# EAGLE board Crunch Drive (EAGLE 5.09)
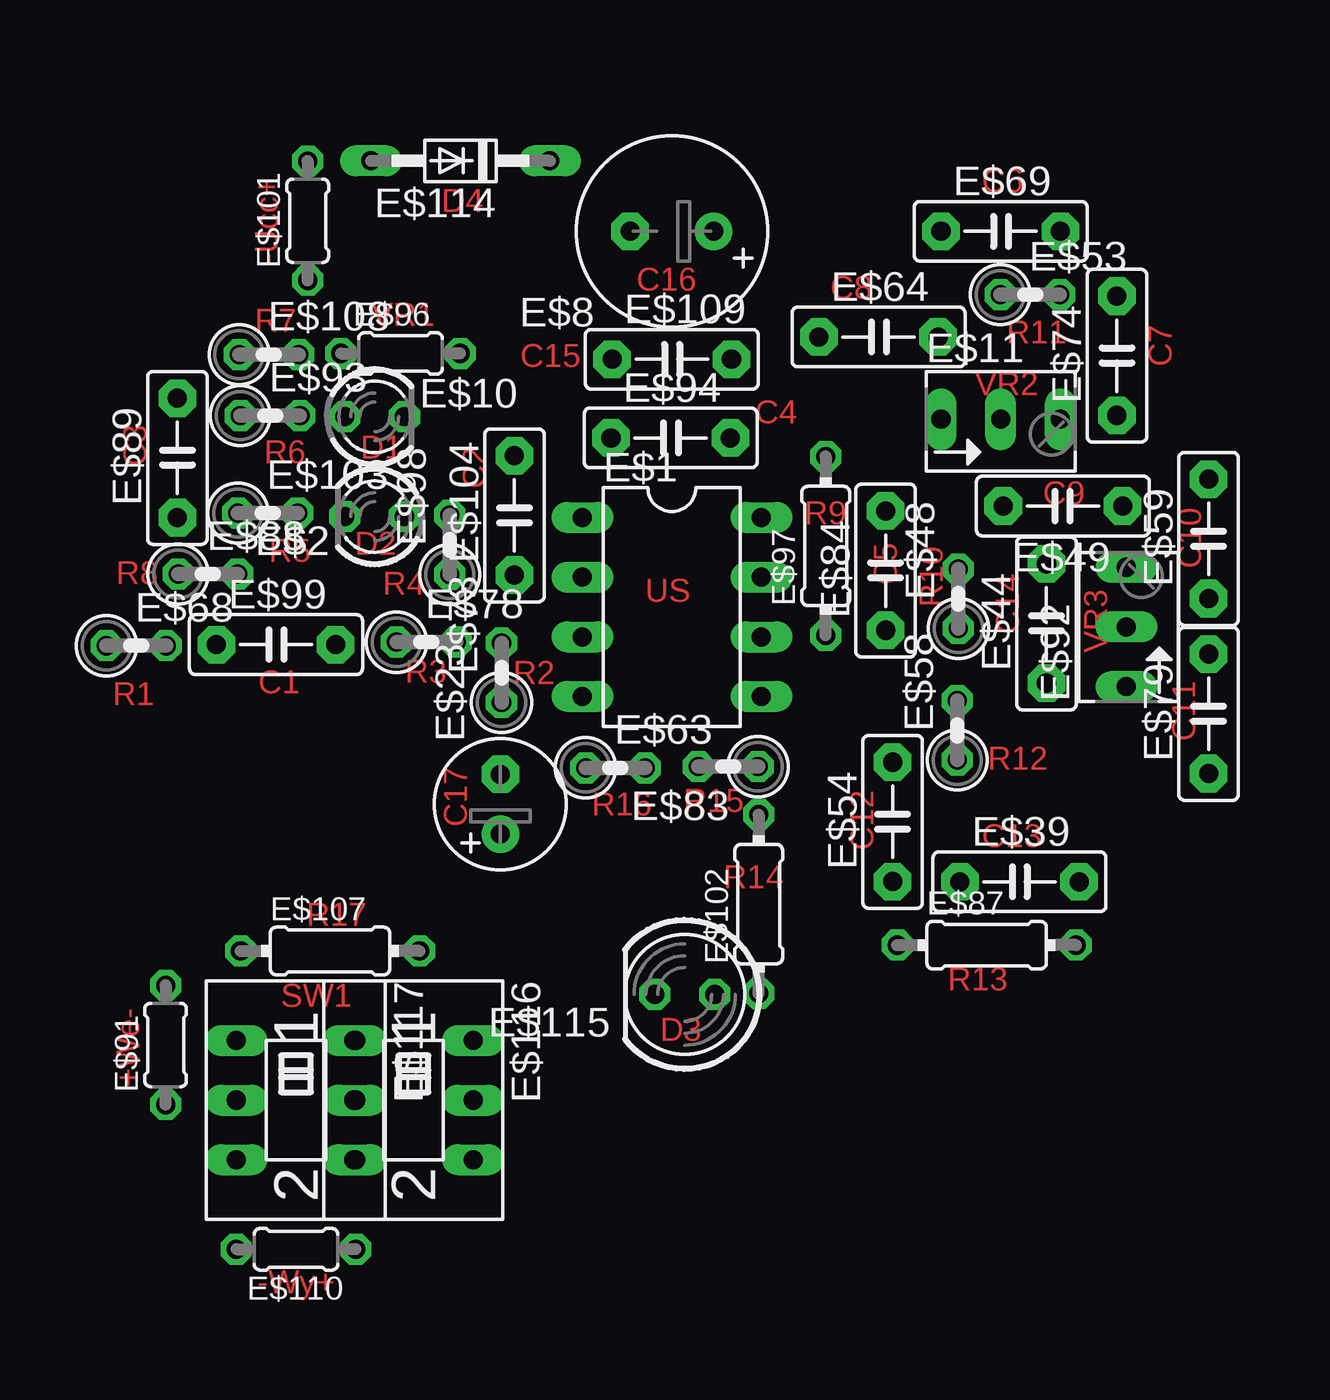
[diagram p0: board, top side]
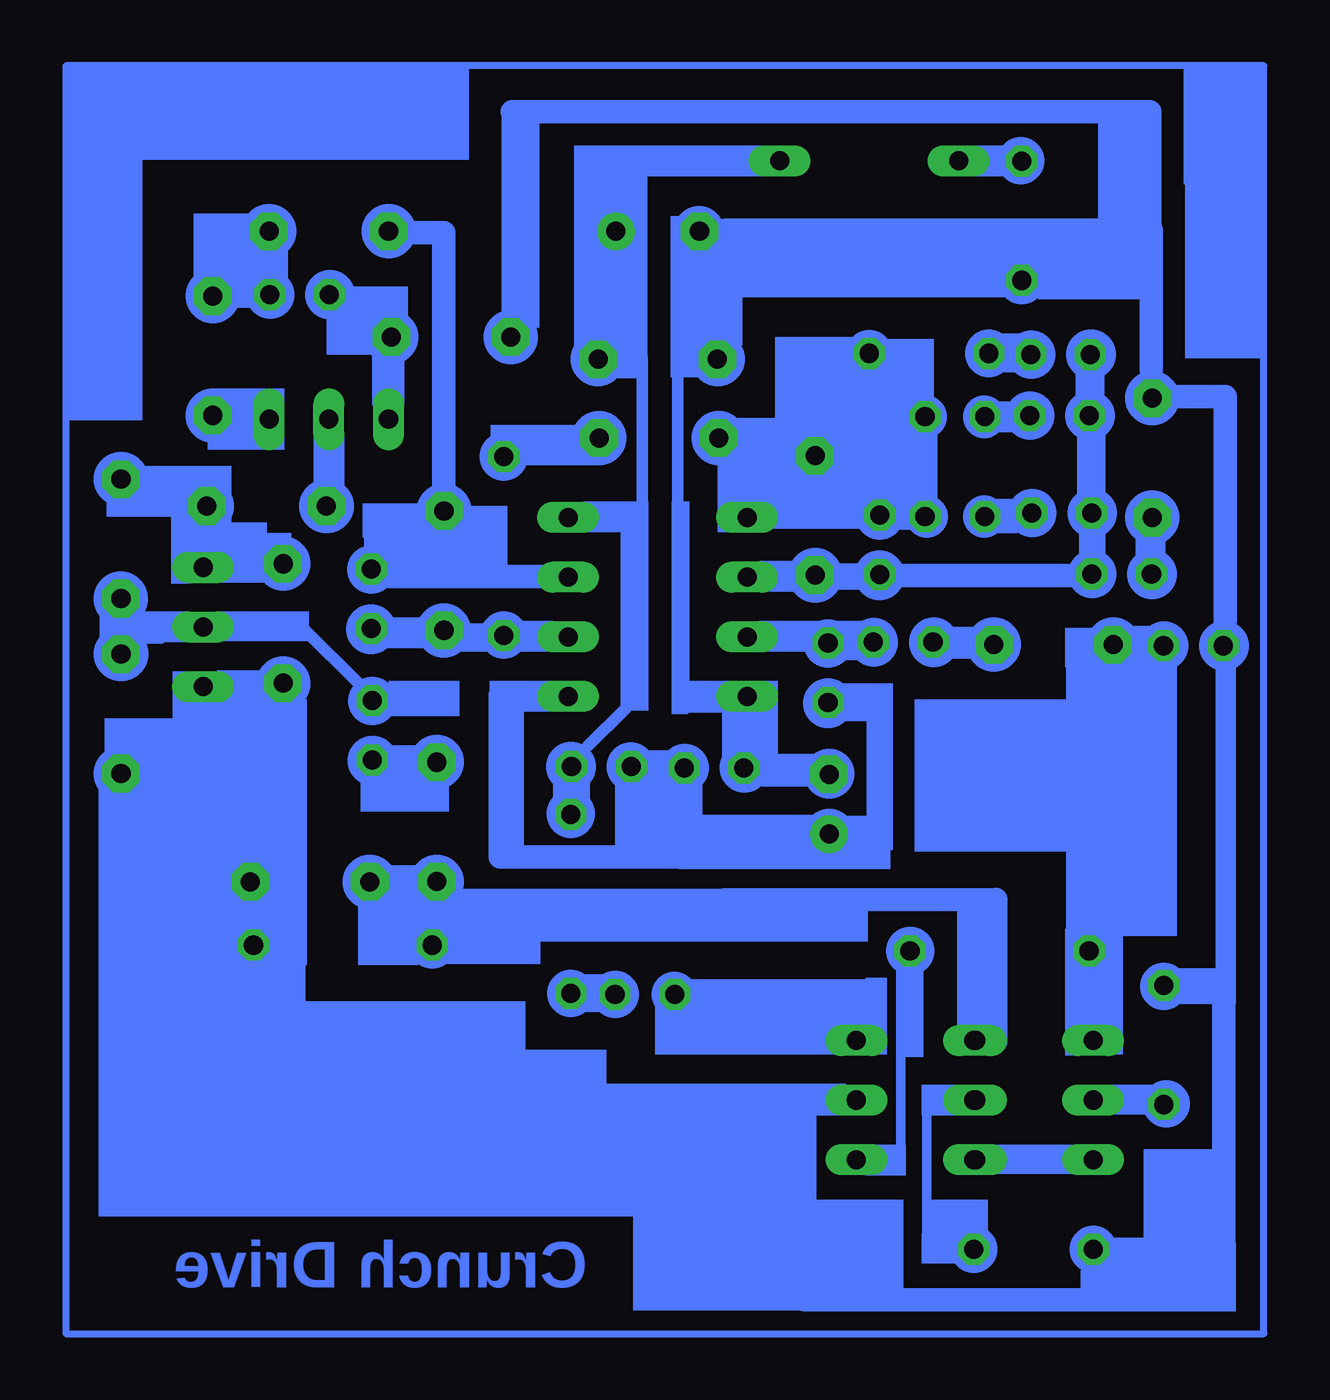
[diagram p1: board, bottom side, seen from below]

No outline drawn. Coordinates in mm, seen from the top.
Copper layers (1*16): Top 0.035mm / dielectric 1.5mm / Bottom 0.035mm
Design rules "default": minimum track width 10mil, minimum drill 24mil, track to track 8mil, track to pad 8mil, pad to pad 8mil, via to via 8mil, smd to smd 8mil, copper to edge 40mil, drill to drill 8mil, minimum pad ring 10mil, minimum via ring 8mil, stop-mask expansion 4mil, vias tented up to drill 0mil, thermal gap 10mil

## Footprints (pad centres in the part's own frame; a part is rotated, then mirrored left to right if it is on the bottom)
DIL08 = drill 0.813 long: 1 -3.81,-3.81; 2 -1.27,-3.81; 3 1.27,-3.81; 4 3.81,-3.81; 5 3.81,3.81; 6 1.27,3.81; 7 -1.27,3.81; 8 -3.81,3.81
LED3MM = drill 0.813 octagon: A -1.27,0; K 1.27,0
E3,5-8 = drill 0.813 pad 1.6 round: + -1.778,0 | drill 0.813 pad 1.6 octagon: - 1.778,0
B64Y = drill 0.813 long: A 2.54,0; E -2.54,0; S 0,0
E2,5-6 = drill 0.813 pad 1.6 round: + -1.27,0 | drill 0.813 pad 1.6 octagon: - 1.27,0
C5B2.5 = drill 0.813 pad 1.6 octagon: 1 -2.54,0; 2 2.54,0
0207/2V = drill 0.813 octagon: 1 -1.27,0; 2 1.27,0
0204/7 = drill 0.813 octagon: 1 -3.81,0; 2 3.81,0
0204/5 = drill 0.813 octagon: 1 -2.54,0; 2 2.54,0
DO34-7 = drill 0.813 long: A 3.81,0; C -3.81,0
LED5MM = drill 0.813 octagon: A -1.27,0; K 1.27,0
A68-A31 = drill 0.813 long: 1 -2.54,-2.54; 2 0,-2.54; 3 2.54,-2.54; 4 -2.54,2.54; 5 0,2.54; 6 2.54,2.54

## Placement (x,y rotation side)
E$1  [DIL08]  26,31 270 top
E$2  [LED3MM]  13.35,34.85 180 top
E$8  [E3,5-8]  26,47 180 top
E$10  [LED3MM]  13.35,39.1 0 top
E$11  [B64Y]  40,39 0 top
E$23  [E2,5-6]  18.7,22.6 90 top
E$39  [C5B2.5]  40.8,19.3 0 top
E$44  [C5B2.5]  41.95,30.3 90 top
E$48  [0207/2V]  38.2,31.35 90 top
E$49  [C5B2.5]  42.65,35.3 180 top
E$53  [0207/2V]  41.25,44.3 0 top
E$54  [C5B2.5]  35.4,21.85 90 top
E$58  [0207/2V]  38.15,25.75 90 top
E$59  [C5B2.5]  48.85,33.9 90 top
E$63  [0207/2V]  23.6,24.15 0 top
E$64  [C5B2.5]  34.8,42.5 0 top
E$68  [0207/2V]  3.2,29.35 0 top
E$69  [C5B2.5]  40,47 0 top
E$73  [0207/2V]  18.75,28.2 90 top
E$74  [C5B2.5]  44.95,41.7 90 top
E$78  [0207/2V]  15.55,29.5 0 top
E$79  [C5B2.5]  48.85,26.45 90 top
E$83  [0207/2V]  28.4,24.2 180 top
E$84  [C5B2.5]  35.1,32.55 90 top
E$87  [0204/7]  39.4,16.6 0 top
E$88  [0207/2V]  6.25,32.4 0 top
E$89  [C5B2.5]  4.95,37.35 90 top
E$91  [0204/5]  4.45,12.35 90 top
E$92  [B64Y]  45.35,30.15 90 top
E$93  [0207/2V]  8.9,39.15 0 top
E$94  [C5B2.5]  25.95,38.2 0 top
E$96  [0204/5]  14.45,41.8 0 top
E$97  [0204/7]  32.55,33.6 90 top
E$98  [0207/2V]  16.55,33.65 90 top
E$99  [C5B2.5]  9.15,29.4 0 top
E$101  [0204/5]  10.5,47.45 90 top
E$102  [0204/7]  29.7,18.35 90 top
E$103  [0207/2V]  8.8,35 0 top
E$104  [C5B2.5]  19.3,34.9 90 top
E$107  [0204/7]  11.45,16.35 0 top
E$108  [0207/2V]  8.85,41.75 0 top
E$109  [C5B2.5]  26,41.55 0 top
E$110  [0204/5]  10,3.65 180 top
E$114  [DO34-7]  17,50 180 top
E$115  [LED5MM]  26.55,14.5 180 top
E$116  [A68-A31]  15,10 270 top
E$117  [A68-A31]  10,10 270 top

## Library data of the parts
E$1 = analog-devices
E$2 E$10 E$115 = led
E$8 E$23 E$48 E$53 E$58 E$63 E$68 E$73 E$78 E$83 E$87 E$88 E$91 E$93 E$96-E$98 E$101-E$103 E$107 E$108 E$110 = rcl
E$11 E$92 = pot
E$39 E$44 E$49 E$54 E$59 E$64 E$69 E$74 E$79 E$84 E$89 E$94 E$99 E$104 E$109 = capacitor-wima
E$114 = diode
E$116 E$117 = switch

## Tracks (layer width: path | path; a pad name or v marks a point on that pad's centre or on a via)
S$1
  Bottom 0.5: 21.35,34.85 19.35,34.85 19.35,36.7
S$2
  Bottom 1: 8.45,32.35 15.55,32.35
S$3
  Bottom 1: 3.85,39.95 1.85,39.95 1.85,30.4
S$4
  Bottom 0.5: 29,25.05 27.35,26.7 27.35,34.8 29,34.8
S$5
  Bottom 0.5: 23.15,27.15 24.9,27.15 24.9,34.6 | 24.9,34.6 24.9,34.65 | 24.9,34.6 25.15,34.6 25.15,41.6 24.5,41.6 24.5,41.55
S$6
  Bottom 0.5: 27.1,35.25 26.65,35.25 26.65,41.6 27.6,41.6 27.6,41.55
S$7
  Bottom 0.5: 17.95,26.85 16.55,26.85 16.55,21.2 17.75,21.2
S$8
  Bottom 0.5: 19.65,21.25 24.85,21.25 24.85,23.35
S$9
  Bottom 1: 23.1,47.05 5,47.05 5,41.1
S$10
  Bottom 1: 21.7,50.05 27.75,50.05 27.75,48.1
S$11
  Bottom 1: 30.8,27.25 32.7,27.25 32.7,20.35 25.05,20.35
S$12
  Bottom 1: 29.45,38.25 32.55,38.25
S$13
  Bottom 1: 30.7,32.3 35.1,32.3 35.1,34.15
S$14
  Bottom 1: 1.9,14.85 1.9,3.65 6.45,3.65
S$15
  Bottom 0.4: 16.6,7.6 15.65,7.6 15.65,15.7
S$16
  Bottom 0.4: 13.55,9.95 14.55,9.95 14.55,3.55 13.35,3.55 13.35,3.65
S$17
  Bottom 1: 6.6,28.25 6.7,28.25 6.7,16.8
S$18
  Bottom 1: 11.6,12.5 11.6,18.55 34.9,18.5
S$19
  Bottom 1: 36.4,46.95 35.1,46.95 35.1,36.25
S$20
  Bottom 1: 32.15,43.9 32.15,51.95
S$21
  Bottom 1: 7.5,2.65 7.5,1.5 19.75,1.5 19.75,10.05 18.45,10.05
S$22
  Bottom 0.5: 44.3,30.15 41.15,30.15 38.65,27.65
S$23
  Bottom 0.3: 0.2,0.05 0.2,54.05 51.2,54.05 51.2,0.05 0.2,0.05
S$24
  Bottom 1: 32.2,52.1 5.05,52.1 5.05,46.55
(copper drawn outside any net)
  shapes: Bottom area x168, Bottom circle x82

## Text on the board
Top: C6 | D4 | -Ucc+ | C16 | C8 | R7 | VR1 | R11 | C15 | C7 | VR2 | C4 | C3 | R6 | D1 | C2 | C9 | R9 | R5 | D2 | C10 | R8 | R4 | US | C5 | R10 | C14 | VR3 | R3 | R2 | R1 | C1 | C11 | R12 | C17 | R16 | R15 | C12 | C13 | R14 | R17 | R13 | SW1 | D3 | +We- | -Wy+
Bottom: Crunch Drive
